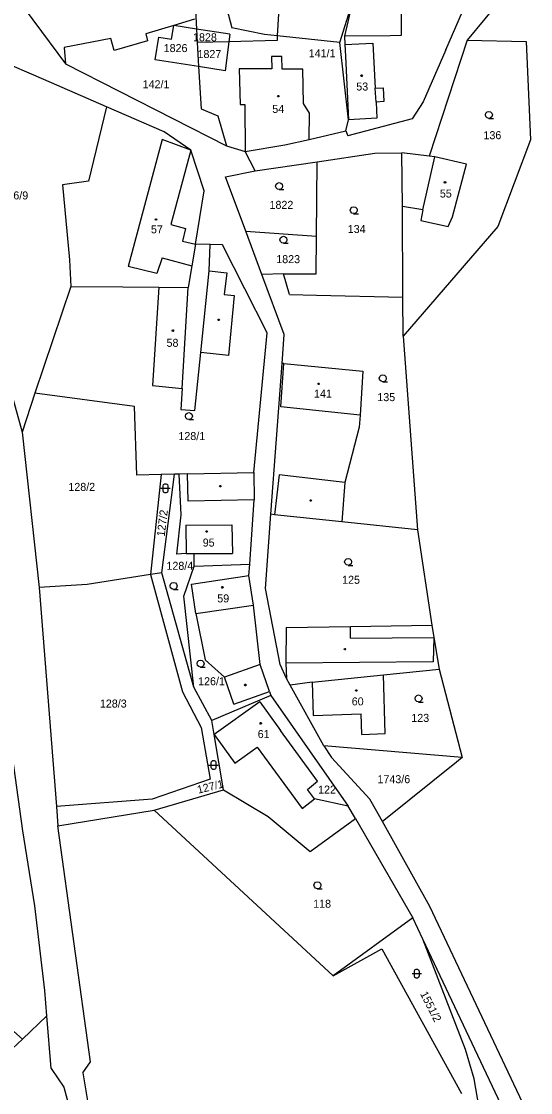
# Model space of a CAD drawing. Extents: x -799786 to -795190, y -1021716 to -1017834.
# Drawn here: x -797767.7 to -797659.5, y -1019141.2 to -1018913.6 of the extents above; entities that cross this region are included whole.
import ezdxf

# ---------------------------------------------------------------- set-up
doc = ezdxf.new("R2010")
doc.units = 0
for name, color, linetype in [('Default', 7, 'Continuous'), ('KN_HRANICE', 7, 'Continuous'), ('KN_KULTURY', 7, 'Continuous'), ('KN_PARCELY', 7, 'Continuous'), ('KN_SLUCKY', 7, 'Continuous')]:
    doc.layers.add(name, color=color, linetype=linetype)

# ---------------------------------------------------------------- blocks, each defined once
blk = doc.blocks.new('304')
at = {"layer": 'Default'}
blk.add_lwpolyline([(0, 0), (-0.38, 0.1), (-0.65, 0.37), (-0.75, 0.74), (-0.65, 1.11), (-0.38, 1.38), (-0.01, 1.48), (0.36, 1.38), (0.63, 1.11), (0.73, 0.73), (0.63, 0.35), (0.36, 0.08), (-0.02, -0.02), (0.98, -0.02)], dxfattribs=at)
blk = doc.blocks.new('316')
at = {"layer": 'Default'}
for points in [[(-1, 1), (0.27, 1), (1, 1)], [(-0.5, 1.5), (-0.4, 1.79), (-0.15, 1.97), (0.16, 1.97), (0.41, 1.79), (0.51, 1.5), (0.51, 0.5), (0.41, 0.21), (0.16, 0.03), (-0.15, 0.03), (-0.4, 0.21), (-0.5, 0.5), (-0.5, 1.5)]]:
    blk.add_lwpolyline(points, dxfattribs=at)
blk = doc.blocks.new('NAHRADNI_SYMBOL')
at = {"layer": 'Default'}
blk.add_lwpolyline([(0.09, 0.15), (0.18, 0), (0.09, -0.15), (-0.09, -0.15), (-0.18, 0), (-0.09, 0.15), (0.09, 0.15)], dxfattribs=at)
blk = doc.blocks.new('402')
at = {"layer": 'Default'}
blk.add_lwpolyline([(0.09, 0.15), (0.18, 0), (0.09, -0.15), (-0.09, -0.15), (-0.18, 0), (-0.09, 0.15), (0.09, 0.15)], dxfattribs=at)

msp = doc.modelspace()

# ---------------------------------------------------------------- linework, layer by layer
at = {"layer": 'KN_HRANICE'}
for p, q in [((-797731.32, -1018897.77), (-797730.45, -1018915.2)), ((-797712.31, -1018899.12), (-797713.28, -1018916.65)), ((-797659.63, -1018901.44), (-797672.91, -1018917.57)), ((-797724.84, -1018907.79), (-797722.95, -1018914.98)), ((-797700.01, -1018918.03), (-797697.37, -1018909.72)), ((-797677.48, -1018919.62), (-797673.23, -1018909.82)), ((-797766.88, -1018911.02), (-797758.32, -1018922.62)), ((-797730.9, -1018913.14), (-797735.28, -1018914.44)), ((-797735.28, -1018914.44), (-797741.24, -1018916.21)), ((-797735.78, -1018917.32), (-797735.28, -1018914.44)), ((-797730.45, -1018915.2), (-797735.28, -1018914.44)), ((-797730.45, -1018915.2), (-797730.31, -1018918.07)), ((-797723.38, -1018916.31), (-797730.45, -1018915.2)), ((-797716.01, -1018916.37), (-797722.95, -1018914.98)), ((-797748.68, -1018917.21), (-797758.6, -1018919.16)), ((-797747.94, -1018919.74), (-797748.68, -1018917.21)), ((-797740.87, -1018917.74), (-797747.94, -1018919.74)), ((-797741.24, -1018916.21), (-797740.87, -1018917.74)), ((-797739.25, -1018921.77), (-797738.48, -1018916.9)), ((-797738.48, -1018916.9), (-797735.78, -1018917.32)), ((-797723.38, -1018916.31), (-797723.59, -1018917.91)), ((-797713.34, -1018917.67), (-797723.59, -1018917.91)), ((-797713.28, -1018916.65), (-797716.01, -1018916.37)), ((-797713.28, -1018916.65), (-797713.34, -1018917.67)), ((-797700.01, -1018918.03), (-797713.28, -1018916.65)), ((-797672.91, -1018917.57), (-797680.99, -1018942.22)), ((-797672.91, -1018917.57), (-797660.4, -1018917.82)), ((-797762.92, -1018925.93), (-797776.98, -1018919.85)), ((-797758.6, -1018919.16), (-797758.32, -1018922.62)), ((-797723.59, -1018917.91), (-797730.31, -1018918.07)), ((-797730.31, -1018918.07), (-797730.01, -1018923.19)), ((-797723.59, -1018917.91), (-797724.39, -1018924.05)), ((-797698.15, -1018934.52), (-797700.01, -1018918.03)), ((-797677.48, -1018919.62), (-797682.27, -1018930.69)), ((-797660.4, -1018917.82), (-797659.47, -1018938.77)), ((-797730.01, -1018923.19), (-797739.25, -1018921.77)), ((-797712.31, -1018921.02), (-797714.51, -1018921.02)), ((-797714.51, -1018921.02), (-797714.46, -1018923.63)), ((-797712.22, -1018923.73), (-797712.31, -1018921.02)), ((-797758.32, -1018922.62), (-797724.08, -1018940.05)), ((-797730.01, -1018923.19), (-797729.48, -1018932.14)), ((-797724.39, -1018924.05), (-797730.01, -1018923.19)), ((-797714.46, -1018923.63), (-797721.39, -1018923.63)), ((-797721.39, -1018923.63), (-797721.19, -1018931.21)), ((-797707.89, -1018923.73), (-797712.22, -1018923.73)), ((-797707.69, -1018931.01), (-797707.89, -1018923.73)), ((-797749.58, -1018931.7), (-797762.92, -1018925.93)), ((-797721.19, -1018931.21), (-797720.19, -1018931.21)), ((-797720.19, -1018931.21), (-797720.08, -1018941.25)), ((-797706.43, -1018933.07), (-797707.69, -1018931.01)), ((-797682.27, -1018930.69), (-797684.66, -1018934.28)), ((-797749.58, -1018931.7), (-797753.4, -1018947.5)), ((-797737.34, -1018937.04), (-797749.58, -1018931.7)), ((-797729.48, -1018932.14), (-797725.9, -1018933.66)), ((-797725.9, -1018933.66), (-797724.08, -1018940.05)), ((-797706.53, -1018938.7), (-797706.43, -1018933.07)), ((-797698.69, -1018936.85), (-797698.15, -1018934.52)), ((-797684.66, -1018934.28), (-797698.33, -1018937.87)), ((-797731.68, -1018940.92), (-797737.34, -1018937.04)), ((-797706.53, -1018938.7), (-797698.69, -1018936.85)), ((-797698.69, -1018936.85), (-797698.33, -1018937.87)), ((-797724.08, -1018940.05), (-797720.08, -1018941.25)), ((-797720.08, -1018941.25), (-797711.7, -1018939.78)), ((-797711.7, -1018939.78), (-797706.53, -1018938.7)), ((-797659.47, -1018938.77), (-797666.45, -1018957.15)), ((-797728.86, -1018949.61), (-797731.68, -1018940.92)), ((-797717.98, -1018945.31), (-797720.08, -1018941.25)), ((-797704.82, -1018943.39), (-797692.55, -1018941.59)), ((-797692.55, -1018941.59), (-797686.79, -1018941.52)), ((-797680.99, -1018942.22), (-797686.79, -1018941.52)), ((-797686.71, -1018952.92), (-797686.79, -1018941.52)), ((-797679.78, -1018942.37), (-797680.99, -1018942.22)), ((-797673.05, -1018943.89), (-797679.78, -1018942.37)), ((-797717.98, -1018945.31), (-797704.82, -1018943.39)), ((-797704.95, -1018959.25), (-797704.82, -1018943.39)), ((-797676.03, -1018955.1), (-797673.05, -1018943.89)), ((-797724.29, -1018946.6), (-797717.98, -1018945.31)), ((-797719.98, -1018958.14), (-797724.29, -1018946.6)), ((-797753.4, -1018947.5), (-797758.92, -1018948.29)), ((-797758.92, -1018948.29), (-797757.44, -1018964.21)), ((-797730.65, -1018960.92), (-797728.86, -1018949.61)), ((-797682.38, -1018953.64), (-797686.71, -1018952.92)), ((-797686.58, -1018972.17), (-797686.71, -1018952.92)), ((-797719.98, -1018958.14), (-797704.95, -1018959.25)), ((-797716.55, -1018967.33), (-797719.98, -1018958.14)), ((-797666.45, -1018957.15), (-797686.53, -1018980.43)), ((-797730.65, -1018960.92), (-797731.44, -1018965.53)), ((-797727.52, -1018961), (-797730.65, -1018960.92)), ((-797705.02, -1018967.24), (-797704.95, -1018959.25)), ((-797727.73, -1018966.59), (-797727.52, -1018961)), ((-797724.91, -1018961.07), (-797727.52, -1018961)), ((-797715.47, -1018979.74), (-797724.91, -1018961.07)), ((-797757.44, -1018964.21), (-797757.14, -1018969.88)), ((-797731.44, -1018965.53), (-797732.22, -1018970.1)), ((-797727.73, -1018966.59), (-797724.04, -1018966.98)), ((-797724.04, -1018966.98), (-797724.57, -1018971.59)), ((-797711.97, -1018967.24), (-797716.55, -1018967.33)), ((-797711.82, -1018980.09), (-797716.55, -1018967.33)), ((-797710.68, -1018971.61), (-797711.97, -1018967.24)), ((-797711.97, -1018967.24), (-797705.02, -1018967.24)), ((-797757.14, -1018969.88), (-797764.79, -1018992.58)), ((-797757.14, -1018969.88), (-797746.09, -1018969.98)), ((-797746.09, -1018969.98), (-797738.43, -1018970.05)), ((-797738.43, -1018970.05), (-797739.77, -1018990.94)), ((-797738.43, -1018970.05), (-797732.22, -1018970.1)), ((-797724.57, -1018971.59), (-797722.46, -1018971.85)), ((-797722.46, -1018971.85), (-797723.65, -1018984.56)), ((-797710.68, -1018971.61), (-797704.94, -1018971.74)), ((-797704.94, -1018971.74), (-797686.58, -1018972.17)), ((-797686.53, -1018980.43), (-797686.58, -1018972.17)), ((-797718.27, -1019009.45), (-797715.47, -1018979.74)), ((-797712.28, -1018986.24), (-797711.82, -1018980.09)), ((-797686.53, -1018980.43), (-797683.48, -1019021.62)), ((-797730.82, -1018996.28), (-797729.54, -1018983.96)), ((-797723.65, -1018984.56), (-797729.54, -1018983.96)), ((-797714.66, -1019018.32), (-797712.28, -1018986.24)), ((-797711.89, -1018986.28), (-797712.28, -1018986.24)), ((-797711.89, -1018986.28), (-797695.14, -1018987.88)), ((-797695.14, -1018987.88), (-797695.71, -1018997.23)), ((-797764.79, -1018992.58), (-797767.5, -1019000.85)), ((-797743.62, -1018995.39), (-797764.79, -1018992.58)), ((-797739.77, -1018990.94), (-797733.52, -1018991.6)), ((-797733.52, -1018991.6), (-797733.78, -1018996.07)), ((-797769.56, -1018993.42), (-797767.5, -1019000.85)), ((-797743.1, -1019010.02), (-797743.62, -1018995.39)), ((-797733.78, -1018996.07), (-797730.82, -1018996.28)), ((-797695.71, -1018997.23), (-797695.86, -1018999.77)), ((-797767.5, -1019000.85), (-797763.88, -1019033.88)), ((-797695.86, -1018999.77), (-797698.94, -1019011.56)), ((-797737.93, -1019009.88), (-797743.1, -1019010.02)), ((-797737.93, -1019009.88), (-797740.22, -1019031.12)), ((-797735.1, -1019009.8), (-797737.93, -1019009.88)), ((-797737.82, -1019030.76), (-797735.1, -1019009.8)), ((-797734.15, -1019009.77), (-797735.1, -1019009.8)), ((-797732.37, -1019009.72), (-797734.15, -1019009.77)), ((-797733.72, -1019018.4), (-797734.15, -1019009.77)), ((-797732.37, -1019009.72), (-797718.27, -1019009.45)), ((-797718.27, -1019009.45), (-797718.21, -1019015.25)), ((-797698.94, -1019011.56), (-797699.6, -1019019.91)), ((-797719.15, -1019028.88), (-797718.21, -1019015.25)), ((-797734.64, -1019026.76), (-797733.72, -1019018.4)), ((-797715.77, -1019034.06), (-797714.66, -1019018.32)), ((-797713.9, -1019018.4), (-797714.66, -1019018.32)), ((-797699.6, -1019019.91), (-797713.9, -1019018.4)), ((-797683.48, -1019021.62), (-797699.6, -1019019.91)), ((-797683.48, -1019021.62), (-797680.44, -1019041.9)), ((-797732.66, -1019026.68), (-797734.64, -1019026.76)), ((-797732.66, -1019026.68), (-797730.94, -1019026.68)), ((-797730.96, -1019029.36), (-797730.94, -1019026.68)), ((-797730.96, -1019029.36), (-797719.15, -1019028.88)), ((-797719.32, -1019031.35), (-797719.15, -1019028.88)), ((-797740.22, -1019031.12), (-797753.7, -1019033.22)), ((-797737.82, -1019030.76), (-797740.22, -1019031.12)), ((-797740.22, -1019031.12), (-797733.41, -1019056.02)), ((-797731.05, -1019055.08), (-797737.82, -1019030.76)), ((-797733.17, -1019035.71), (-797730.96, -1019029.36)), ((-797731.54, -1019033.13), (-797719.32, -1019031.35)), ((-797718.37, -1019037.64), (-797719.32, -1019031.35)), ((-797753.7, -1019033.22), (-797763.88, -1019033.88)), ((-797730.59, -1019039.42), (-797731.54, -1019033.13)), ((-797763.88, -1019033.88), (-797760.21, -1019080.44)), ((-797731.05, -1019055.08), (-797733.17, -1019035.71)), ((-797712.71, -1019050.2), (-797715.77, -1019034.06)), ((-797716.9, -1019050.24), (-797718.37, -1019037.64)), ((-797730.59, -1019039.42), (-797728.63, -1019049.27)), ((-797711.4, -1019042.39), (-797711.48, -1019049.94)), ((-797711.4, -1019042.39), (-797697.7, -1019042.17)), ((-797697.7, -1019042.17), (-797680.44, -1019041.9)), ((-797680.44, -1019041.9), (-797680, -1019044.5)), ((-797680, -1019044.5), (-797678.87, -1019051.22)), ((-797728.63, -1019049.27), (-797724.48, -1019052.89)), ((-797714.97, -1019056), (-797716.9, -1019050.24)), ((-797711.35, -1019053.21), (-797712.71, -1019050.2)), ((-797711.48, -1019049.94), (-797711.35, -1019053.21)), ((-797690.74, -1019052.44), (-797678.87, -1019051.22)), ((-797678.87, -1019051.22), (-797674.03, -1019070.02)), ((-797767.35, -1019085.59), (-797771.72, -1019053.85)), ((-797722.55, -1019058.65), (-797724.48, -1019052.89)), ((-797710.56, -1019054.63), (-797711.35, -1019053.21)), ((-797705.85, -1019054), (-797710.56, -1019054.63)), ((-797705.85, -1019054), (-797705.67, -1019061.08)), ((-797690.4, -1019064.87), (-797690.74, -1019052.44)), ((-797733.41, -1019056.02), (-797729.49, -1019063.62)), ((-797727.17, -1019062.15), (-797731.05, -1019055.08)), ((-797722.55, -1019058.65), (-797714.97, -1019056)), ((-797714.97, -1019056), (-797714.65, -1019056.85)), ((-797703.39, -1019067.52), (-797710.56, -1019054.63)), ((-797714.65, -1019056.85), (-797727.17, -1019062.15)), ((-797717.03, -1019058.18), (-797726.71, -1019065.14)), ((-797717.03, -1019058.18), (-797712.62, -1019064.24)), ((-797714.65, -1019056.85), (-797698.24, -1019080.35)), ((-797705.67, -1019061.08), (-797695.44, -1019060.72)), ((-797695.33, -1019065.08), (-797695.44, -1019060.72)), ((-797726.71, -1019065.14), (-797727.17, -1019062.15)), ((-797729.49, -1019063.62), (-797727.53, -1019074.63)), ((-797724.75, -1019076.86), (-797726.71, -1019065.14)), ((-797704.74, -1019075.02), (-797712.62, -1019064.24)), ((-797695.33, -1019065.08), (-797690.4, -1019064.87)), ((-797674.03, -1019070.02), (-797703.39, -1019067.52)), ((-797703.39, -1019067.52), (-797701.8, -1019069.99)), ((-797701.8, -1019069.99), (-797693.59, -1019078.87)), ((-797674.03, -1019070.02), (-797675.2, -1019070.96)), ((-797675.2, -1019070.96), (-797690.33, -1019083.12)), ((-797727.53, -1019074.63), (-797739.91, -1019078.87)), ((-797739.46, -1019081.2), (-797724.75, -1019076.86)), ((-797724.75, -1019076.86), (-797715.2, -1019082.5)), ((-797706.86, -1019076.82), (-797704.74, -1019075.02)), ((-797705.37, -1019078.78), (-797706.86, -1019076.82)), ((-797739.91, -1019078.87), (-797760.21, -1019080.44)), ((-797698.24, -1019080.35), (-797705.37, -1019078.78)), ((-797690.94, -1019083.61), (-797693.59, -1019078.87)), ((-797760.21, -1019080.44), (-797759.89, -1019084.49)), ((-797759.89, -1019084.49), (-797739.46, -1019081.2)), ((-797739.46, -1019081.2), (-797701.45, -1019116.42)), ((-797696.65, -1019082.97), (-797698.24, -1019080.35)), ((-797715.2, -1019082.5), (-797706.28, -1019089.94)), ((-797706.28, -1019089.94), (-797696.65, -1019082.97)), ((-797696.65, -1019082.97), (-797684.52, -1019104.04)), ((-797690.33, -1019083.12), (-797690.94, -1019083.61)), ((-797680.85, -1019101.69), (-797690.94, -1019083.61)), ((-797764.83, -1019101.5), (-797767.35, -1019085.59)), ((-797753.01, -1019134.64), (-797759.89, -1019084.49)), ((-797762.68, -1019119.51), (-797764.83, -1019101.5)), ((-797659.88, -1019146), (-797680.85, -1019101.69)), ((-797684.52, -1019104.04), (-797701.45, -1019116.42)), ((-797682.36, -1019108.61), (-797684.52, -1019104.04)), ((-797664.24, -1019146.89), (-797682.36, -1019108.61)), ((-797701.45, -1019116.42), (-797691.05, -1019110.67)), ((-797691.05, -1019110.67), (-797674.12, -1019141.38)), ((-797762.23, -1019124.92), (-797762.68, -1019119.51)), ((-797767.46, -1019129.82), (-797770.51, -1019127.09)), ((-797767.46, -1019129.82), (-797762.23, -1019124.92)), ((-797761.3, -1019136.05), (-797762.23, -1019124.92)), ((-797776.38, -1019138.19), (-797767.46, -1019129.82)), ((-797761.3, -1019136.05), (-797758.63, -1019140.07)), ((-797754.62, -1019137), (-797753.01, -1019134.64)), ((-797754.62, -1019137), (-797752.49, -1019149.73)), ((-797758.63, -1019140.07), (-797754.77, -1019154.63))]:
    msp.add_line(p, q, dxfattribs=at)
for points in [[(-797682.38, -1018953.64), (-797682.78, -1018955.87), (-797676.96, -1018957.13), (-797676.03, -1018955.1)], [(-797671.05, -1019184.15), (-797669.23, -1019177.06), (-797668.82, -1019170.8), (-797669.25, -1019151.05), (-797671.49, -1019138.3), (-797673.31, -1019132.02), (-797682.36, -1019108.61)]]:
    msp.add_lwpolyline(points, dxfattribs=at)
at = {"layer": 'KN_SLUCKY'}
for p, q in [((-797697.37, -1018909.72), (-797699.02, -1018916.69)), ((-797686.97, -1018911.69), (-797686.94, -1018916.61)), ((-797689.32, -1018916.62), (-797699.02, -1018916.69)), ((-797699.02, -1018916.69), (-797698.95, -1018918.47)), ((-797686.94, -1018916.61), (-797689.32, -1018916.62)), ((-797698.95, -1018918.47), (-797692.96, -1018918.23)), ((-797698.95, -1018918.47), (-797698.82, -1018921)), ((-797692.96, -1018918.23), (-797692.46, -1018927.76)), ((-797698.82, -1018921), (-797698.15, -1018934.52)), ((-797692.46, -1018927.76), (-797690.78, -1018927.68)), ((-797692.29, -1018930.72), (-797692.46, -1018927.76)), ((-797690.78, -1018927.68), (-797690.63, -1018930.63)), ((-797690.63, -1018930.63), (-797692.29, -1018930.72)), ((-797692.29, -1018930.72), (-797692.11, -1018934.14)), ((-797692.11, -1018934.14), (-797698.15, -1018934.52)), ((-797737.78, -1018938.68), (-797744.95, -1018965.66)), ((-797731.68, -1018940.92), (-797737.78, -1018938.68)), ((-797731.68, -1018940.92), (-797735.91, -1018956.71)), ((-797682.38, -1018953.64), (-797679.78, -1018942.37)), ((-797735.91, -1018956.71), (-797732.78, -1018957.6)), ((-797732.78, -1018957.6), (-797733.44, -1018960.31)), ((-797733.44, -1018960.31), (-797730.65, -1018960.92)), ((-797737.73, -1018963.8), (-797738.91, -1018967.16)), ((-797737.73, -1018963.8), (-797731.44, -1018965.53)), ((-797738.91, -1018967.16), (-797744.95, -1018965.66)), ((-797729.54, -1018983.96), (-797727.73, -1018966.59)), ((-797733.52, -1018991.6), (-797732.22, -1018970.1)), ((-797712.55, -1018995.51), (-797711.89, -1018986.28)), ((-797695.71, -1018997.23), (-797712.55, -1018995.51)), ((-797732.25, -1019015.51), (-797732.37, -1019009.72)), ((-797712.89, -1019009.9), (-797713.9, -1019018.4)), ((-797698.94, -1019011.56), (-797712.89, -1019009.9)), ((-797718.21, -1019015.25), (-797732.25, -1019015.51)), ((-797732.71, -1019020.62), (-797722.93, -1019020.57)), ((-797732.71, -1019020.62), (-797732.66, -1019026.68)), ((-797722.93, -1019020.57), (-797722.81, -1019026.68)), ((-797730.94, -1019026.68), (-797722.81, -1019026.68)), ((-797730.59, -1019039.42), (-797718.37, -1019037.64)), ((-797697.72, -1019044.67), (-797697.7, -1019042.17)), ((-797697.72, -1019044.67), (-797680, -1019044.5)), ((-797680, -1019044.5), (-797680.17, -1019049.64)), ((-797680.17, -1019049.64), (-797711.48, -1019049.94)), ((-797716.9, -1019050.24), (-797724.48, -1019052.89)), ((-797705.85, -1019054), (-797690.74, -1019052.44)), ((-797726.71, -1019065.14), (-797722.3, -1019071.2)), ((-797722.3, -1019071.2), (-797717.59, -1019067.81)), ((-797717.59, -1019067.81), (-797708.03, -1019080.82)), ((-797708.03, -1019080.82), (-797705.37, -1019078.78))]:
    msp.add_line(p, q, dxfattribs=at)

# ---------------------------------------------------------------- block references
at = {"layer": 'KN_KULTURY'}
for name, p in [('402', (-797695.39, -1018925.11)), ('NAHRADNI_SYMBOL', (-797713.06, -1018929.47)), ('304', (-797668.32, -1018934.18)), ('304', (-797712.89, -1018949.3)), ('402', (-797677.64, -1018947.78)), ('304', (-797697.04, -1018954.43)), ('402', (-797739.05, -1018955.65)), ('304', (-797711.97, -1018960.71)), ('402', (-797725.74, -1018977)), ('402', (-797735.48, -1018979.3)), ('402', (-797704.52, -1018990.6)), ('304', (-797690.87, -1018990.16)), ('304', (-797732.06, -1018998.18)), ('316', (-797737.06, -1019013.79)), ('402', (-797725.39, -1019012.32)), ('402', (-797706.17, -1019015.39)), ('402', (-797728.29, -1019021.99)), ('304', (-797698.23, -1019029.16)), ('304', (-797735.3, -1019034.28)), ('402', (-797724.94, -1019033.83)), ('402', (-797698.93, -1019046.95)), ('304', (-797729.59, -1019050.79)), ('402', (-797720.09, -1019054.59)), ('402', (-797696.49, -1019055.78)), ('304', (-797683.27, -1019058.19)), ('402', (-797716.8, -1019062.73)), ('316', (-797726.83, -1019072.59)), ('304', (-797704.76, -1019097.88)), ('316', (-797683.66, -1019116.92))]:
    msp.add_blockref(name, p, dxfattribs=at)

# ---------------------------------------------------------------- texts
at = {"layer": 'KN_PARCELY'}
for s, p in [('1828', (-797731.19, -1018917.8)), ('1826', (-797737.43, -1018920.1)), ('1827', (-797730.24, -1018921.37)), ('141/1', (-797706.61, -1018921.21)), ('142/1', (-797741.9, -1018927.79)), ('53', (-797696.5, -1018928.27)), ('54', (-797714.35, -1018933.03)), ('136', (-797669.48, -1018938.61)), ('55', (-797678.75, -1018951)), ('116/9', (-797771.9, -1018951.41)), ('1822', (-797714.94, -1018953.41)), ('57', (-797740.13, -1018958.61)), ('134', (-797698.32, -1018958.54)), ('1823', (-797713.51, -1018964.95)), ('58', (-797736.82, -1018982.73)), ('141', (-797705.49, -1018993.53)), ('135', (-797692.03, -1018994.27)), ('128/1', (-797734.3, -1019002.54)), ('128/2', (-797757.68, -1019013.34)), ('95', (-797729.13, -1019025.17)), ('128/4', (-797736.84, -1019030.11)), ('125', (-797699.51, -1019033.08)), ('59', (-797726.04, -1019037.04)), ('126/1', (-797730.11, -1019054.64)), ('128/3', (-797750.98, -1019059.38)), ('60', (-797697.47, -1019058.92)), ('123', (-797684.81, -1019062.43)), ('61', (-797717.45, -1019065.86)), ('1743/6', (-797692, -1019075.45)), ('122', (-797704.61, -1019077.66)), ('118', (-797705.66, -1019101.92))]:
    msp.add_text(s, height=1.7, dxfattribs=at).set_placement(p)
for s, rotation, p in [('127/2', 83.193, (-797737.22, -1019023.11)), ('127/1', 13.636, (-797730.09, -1019077.69)), ('1551/2', 296.964, (-797682.99, -1019120.2))]:
    msp.add_text(s, height=1.7, rotation=rotation, dxfattribs=at).set_placement(p)

doc.saveas('drawing.dxf')
